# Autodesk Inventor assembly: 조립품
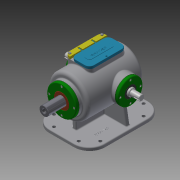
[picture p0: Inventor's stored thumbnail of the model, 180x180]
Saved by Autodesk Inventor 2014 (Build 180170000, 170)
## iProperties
Created: 2019-10
Part Number: 조립품
Document SubType Name: Assembly
Designer: kh
Author: kh
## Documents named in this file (17)
- C:\Users\kh\Desktop\391004V1004\조립품.iam
- C:\Users\kh\Desktop\391004V1004\본체.ipt
- C:\Users\kh\Desktop\391004V1004\가변스프링.ipt
- C:\Users\kh\Desktop\391004V1004\개스킷 A.ipt
- C:\Users\kh\Desktop\391004V1004\개스킷 B.ipt
- C:\Users\kh\Desktop\391004V1004\고정플레이트.ipt
- C:\Users\kh\Desktop\391004V1004\베어링 6205.ipt
- 베어링 6205.ipt
- C:\Users\kh\Desktop\391004V1004\볼트 M4x0.7.ipt
- C:\Users\kh\Desktop\391004V1004\부시.ipt
- C:\Users\kh\Desktop\391004V1004\상부커버.ipt
- C:\Users\kh\Desktop\391004V1004\슬라이드 커버.ipt
- C:\Users\kh\Desktop\391004V1004\슬라이드.ipt
- C:\Users\kh\Desktop\391004V1004\오일 실 25 38 8.ipt
- C:\Users\kh\Desktop\391004V1004\육각머리볼트 M4.ipt
- C:\Users\kh\Desktop\391004V1004\축 커버.ipt
- C:\Users\kh\Desktop\391004V1004\편심축.ipt
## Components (17 placed, 5 different names)
1. 가변스프링:1 — Mate:2, Mate:4, Mate:5
2. 개스킷 A:1 — Insert:15, Insert:16, Insert:17, Insert:18
3. 개스킷 B:1 — Insert:5, Insert:6, Insert:12, Insert:13
4. 고정플레이트:1 — Insert:19, Insert:20, Insert:24, Insert:25, Mate:6
5. 개스킷 B:2 — Insert:4, Insert:7, Insert:10, Insert:11
6. M4x0.7:3 — Insert:21, Angle:1
7. M4x0.7:4
8. M4x0.7:5
9. M4x0.7:6
10. M4x0.7:2 — Insert:23, Angle:3
11. M4x0.7:7
12. M4x0.7:8
13. M4x0.7:9
14. M4x0.7:1 — Insert:22, Angle:2
15. M4x0.7:10
16. M4x0.7:11
17. M4x0.7:12
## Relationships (26: Insert 19, Mate 4, Angle 3)
- Insert:4: 개스킷 B:2
- Insert:5: 개스킷 B:1
- Insert:6: 개스킷 B:1
- Insert:7: 개스킷 B:2
- Insert:10: 개스킷 B:2
- Insert:11: 개스킷 B:2
- Insert:12: 개스킷 B:1
- Insert:13: 개스킷 B:1
- Insert:15: 개스킷 A:1
- Insert:16: 개스킷 A:1
- Mate:2: 가변스프링:1
- Insert:17: 개스킷 A:1
- Insert:18: 개스킷 A:1
- Insert:19: 고정플레이트:1
- Insert:20: 고정플레이트:1
- Insert:21: M4x0.7:3
- Insert:22: M4x0.7:1
- Insert:23: M4x0.7:2
- Angle:1: M4x0.7:3
- Angle:2: M4x0.7:1
- Angle:3: M4x0.7:2
- Insert:24: 고정플레이트:1
- Insert:25: 고정플레이트:1
- Mate:4: 가변스프링:1
- Mate:5: 가변스프링:1
- Mate:6: 고정플레이트:1
